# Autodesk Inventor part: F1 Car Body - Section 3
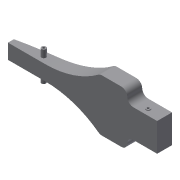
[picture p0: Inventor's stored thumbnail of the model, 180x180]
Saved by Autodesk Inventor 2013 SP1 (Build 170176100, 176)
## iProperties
Created: 2013-01
Part Number: F1 Car Body - Section 3
Material: Generic
Document SubType Name: Modeling
Designer: banachd
Density: 1 g/cm^3
Author: banachd
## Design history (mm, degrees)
sketch "Sketch1"
  geometry: L1 (0, 0)-(200, 0); L2 (200, 0)-(200, 20); L3 (200, 20)-(110, 20); L4 (0, 8)-(0, 0); A1 r 510.167 centre (110, -490.167) between (110, 20) and (0, 8)
  constraints: 8 end point, 2 perpendicular, 2 point on circle, 1 centre point, 1 horizontal, 1 parallel, 1 tangent
  dimensions: "d0" = 200 distance of L1.start L1.end; "d1" = 20 distance of L1.end L2.end; "d2" = 90 distance of L2.end L3.end; "d3" = 8 distance of L4.start L1.start
extrude "Extrusion1" new body sketch "Sketch1" distance "d4" = 35; taper "d5" = 0 deg
sketch "Sketch2"
  geometry: L1 (0, 0)-(200, 0) reference; L2 (0, 35)-(200, 35) reference; L3 (0, 0)-(0, 35) reference; L4 (0, 10)-(50, 10); L5 (200, 35)-(160, 35); L6 (160, 35)-(160, 19); L7 (160, 19)-(200, 19); L8 (200, 19)-(200, 35); A1 r 120 centre (50, 130) between (50, 10) and (123.314, 35)
  constraints: 10 end point, 3 parallel, 2 point on circle, 2 point on line, 1 centre point, 1 horizontal, 1 perpendicular, 1 tangent
  dimensions: "d6" = 50 distance of L4.start L4.end; "d7" = 40 distance of L7.end L6.end; "d8" = 16 distance of L6.end L5.end; "d9" = 10 distance between parallel lines of L4 L1; "d10" = 120 radius of A1
extrude "Extrusion2" cut sketch "Sketch2" stored distance "d11" = 0; taper "d12" = 0 deg
sketch "Sketch3"
  geometry: L1 (0, 0)-(0, 8) reference; L2 (50, 0)-(0, 0) reference; C1 r 3 at (40, 8)
  constraints: 1 centre point
  dimensions: "d13" = 6 diameter of C1; "d15" = 8 distance from line of C1.centre L2; "d17" = 40 distance from line of C1.centre L1
extrude "Extrusion3" join sketch "Sketch3" distance "d18" = 10; taper "d19" = 0 deg
hole "Hole1" diameter "d22" = 3; stored, may be unused: countersink angle "d26" = 90 deg, drill point angle "d28" = 118 deg; dims "d20" = 10, "d21" = 10, "d23" = 6, "d24" = 4, "d25" = 2, "d27" = 8
pattern_linear "Rectangular Pattern1"
fillet "Fillet1" dims "d32" = 8
mirror "Mirror1"
body "Solid1"
